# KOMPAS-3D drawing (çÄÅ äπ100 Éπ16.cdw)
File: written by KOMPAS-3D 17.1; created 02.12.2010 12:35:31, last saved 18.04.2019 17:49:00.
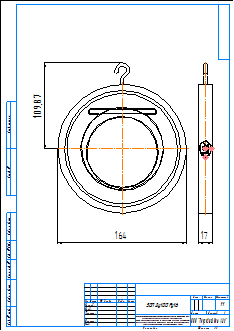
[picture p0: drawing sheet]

Sheet 1: A3, portrait

Title block, sheet 1: name: ЗОП Ду100 Ру16; material: Внимание! Данный продукт является объектом авторского права ООО «Торговый Дом АДЛ». / Запрещается изменение, копирование, распространение / (в том числе путем копирования на другие сайты и ресурсы в Интернете) / или любое иное использование информации и объектов без предварительного / согласия правообладателя (ООО «Торговый Дом АДЛ»).; scale: 1:1; sheets: 1; organisation: ООО "Торговый дом АДЛ"; sheet format: A3; stored path: \\adlc.lan\data\АДЛ_ПКД\3D-модели\ADL production\Клапаны обратные ГРАНЛОК\ЗОП\KOMPAS 2D\ЗОП Ду100 Ру16.cdw

Views: Спереди 1, Проекционный вид 2
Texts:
  bsv
  adl
Dimensions and other numbers on the sheet: 164; 17; 109,87; 1:1; 1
